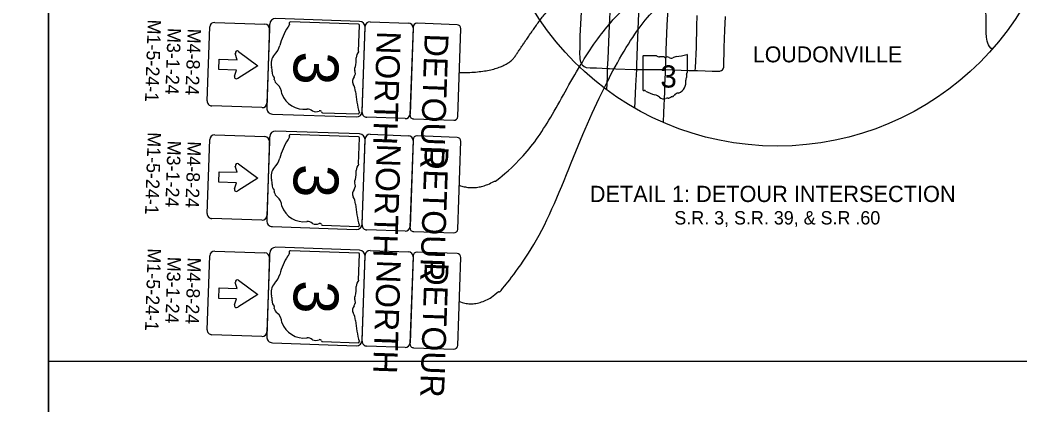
# Model space of a CAD drawing. Extents: x -15.3 to 34, y 0 to 22.
# Drawn here: x 1.2 to 11.66, y 10.54 to 14.57 of the extents above; entities that cross this region are included whole.
import ezdxf

# ---------------------------------------------------------------- set-up
doc = ezdxf.new("R2010")
doc.units = 0
for name, color, linetype in [('GM_X_City_Street', 7, 'Continuous'), ('GM_X_Corporation_Text', 7, 'Continuous'), ('GM_X_State_Route', 7, 'Continuous'), ('GM_X_State_Shield', 7, 'Continuous'), ('SC_Scratch1', 7, 'Continuous'), ('SH_Border', 7, 'Continuous'), ('SH_Text', 7, 'Continuous'), ('SN_P_Signs', 7, 'Continuous')]:
    doc.layers.add(name, color=color, linetype=linetype)

msp = doc.modelspace()

# ---------------------------------------------------------------- linework, layer by layer
at = {"layer": 'GM_X_City_Street'}
for points in [[(11.372, 14.262), (11.357, 14.274), (11.345, 14.29), (11.334, 14.308), (11.326, 14.327), (11.32, 14.348), (11.315, 14.369), (11.312, 14.39), (11.31, 14.433), (11.31, 14.543), (11.307, 14.718), (11.305, 14.784), (11.304, 14.871), (11.302, 14.981), (11.302, 15.108)], [(7.083, 14.101), (7.071, 14.127), (7.062, 14.164), (7.06, 14.233), (7.061, 14.27), (7.062, 14.341), (7.064, 14.4), (7.076, 14.655)], [(7.35, 14.062), (7.354, 14.162), (7.37, 14.512), (7.375, 14.649)], [(7.654, 14.052), (7.655, 14.102), (7.659, 14.189), (7.663, 14.297), (7.675, 14.641)], [(8.267, 14.039), (8.268, 14.068), (8.278, 14.286), (8.284, 14.505), (8.288, 14.615)], [(8.55, 14.049), (8.557, 14.058), (8.562, 14.065), (8.564, 14.075), (8.569, 14.282), (8.576, 14.462), (8.582, 14.604)], [(7.083, 14.101), (7.104, 14.082), (7.127, 14.073), (7.168, 14.069), (7.235, 14.067), (7.294, 14.065), (7.35, 14.062)], [(7.34, 13.839), (7.347, 13.97), (7.35, 14.055), (7.35, 14.062)], [(7.35, 14.062), (7.37, 14.061), (7.434, 14.058), (7.628, 14.052), (7.654, 14.052)], [(7.634, 13.647), (7.641, 13.797), (7.644, 13.884), (7.654, 14.052)], [(7.654, 14.052), (7.707, 14.05), (7.741, 14.05), (7.785, 14.05), (7.844, 14.05), (7.873, 14.05), (7.926, 14.05), (7.956, 14.05)], [(7.956, 14.05), (8.199, 14.041), (8.267, 14.039)], [(8.267, 14.039), (8.291, 14.039), (8.369, 14.037), (8.445, 14.035), (8.522, 14.035), (8.532, 14.038), (8.541, 14.042), (8.55, 14.049)]]:
    msp.add_lwpolyline(points, dxfattribs=at)
at = {"layer": 'GM_X_State_Route'}
msp.add_line((7.933, 13.497), (7.937, 13.6), dxfattribs=at)
msp.add_lwpolyline([(7.937, 13.6), (7.937, 13.601), (7.947, 13.819), (7.95, 13.885), (7.955, 14.015), (7.956, 14.05), (7.957, 14.101), (7.963, 14.254), (7.974, 14.516), (7.978, 14.629), (7.982, 14.735), (7.992, 14.973), (8.002, 15.207), (8.004, 15.235), (8.011, 15.41), (8.016, 15.515), (8.02, 15.607), (8.024, 15.694), (8.03, 15.819)], dxfattribs=at)
at = {"layer": 'GM_X_State_Shield'}
for p, q in [((7.719, 14.189), (7.719, 13.837)), ((7.86, 14.195), (7.724, 14.195)), ((8.184, 14.02), (8.184, 14.204)), ((8.184, 14.02), (8.184, 14.02))]:
    msp.add_line(p, q, dxfattribs=at)
for centre, radius, start, end in [((7.725, 14.19), 0.00538, 98.1301, 188.1301), ((7.892, 14.236), 0.0521, 231.6195, 271.1119), ((7.91, 13.998), 0.187, 80.4867, 94.9883), ((7.952, 14.192), 0.015, 219.7921, 297.1024), ((7.974, 14.151), 0.0313, 54.4667, 119.1411), ((8.015, 14.207), 0.0376, 233.8562, 294.8282), ((8.081, 14.088), 0.099, 97.3462, 120.7689), ((8.018, 14.675), 0.492, 275.8445, 288.9065), ((8.178, 14.205), 0.00517, 351.8621, 97.738), ((8.178, 14.019), 0.00553, 289.6038, 7.7341), ((8.046, 13.919), 0.123, 292.3089, 8.9858), ((8.202, 13.943), 0.0349, 136.8065, 186.9296), ((8.182, 14.006), 0.00799, 107.944, 210.337), ((8.131, 13.983), 0.048, 340.033, 23.6496), ((7.725, 13.836), 0.00542, 171.9584, 258.3066), ((7.726, 13.872), 0.0414, 267.339, 280.6039), ((7.734, 13.817), 0.0149, 29.7484, 93.2717), ((7.923, 14.133), 0.355, 240.4129, 257.1985), ((7.817, 13.679), 0.111, 47.1842, 75.836), ((7.937, 13.815), 0.0706, 230.7004, 286.2918), ((7.978, 13.693), 0.058, 85.6951, 111.2099), ((7.983, 13.789), 0.0376, 268.777, 315.5493), ((8.017, 13.754), 0.0106, 65.7517, 132.6484), ((8.012, 13.803), 0.0398, 282.8732, 323.2771), ((8.098, 13.738), 0.0674, 94.4031, 142.5768)]:
    msp.add_arc(centre, radius, start, end, dxfattribs=at)
at = {"layer": 'SH_Border'}
for points in [[(0.5, 21.5), (1.5, 21.5), (1.5, 0.5), (0.5, 0.5)], [(1.5, 21.5), (33.5, 21.5), (33.5, 0.5), (1.5, 0.5)]]:
    msp.add_lwpolyline(points, close=True, dxfattribs=at)
at = {"layer": 'SH_Text'}
msp.add_line((1.5, 11), (32, 11), dxfattribs=at)
msp.add_circle((9.125, 16.25), 3, dxfattribs=at)
for points in [[(5.798, 12.84), (6.285, 12.661), (7.504, 14.941), (8.796, 15.157), (8.904, 15.618), (9.02, 15.655)], [(5.798, 14.018), (6.273, 14.018), (6.507, 14.381), (6.828, 14.819), (8.206, 15.3), (8.557, 15.349), (8.793, 15.599), (8.86, 15.655)], [(5.798, 11.625), (6.317, 11.418), (7.553, 14.563), (8.511, 15.093), (9.076, 15.063), (9.152, 15.642), (9.308, 15.639)]]:
    msp.add_open_spline(points, degree=2, dxfattribs=at)
at = {"layer": 'SN_P_Signs'}
for p, q in [((3.24, 14.544), (3.764, 14.526)), ((4.743, 14.524), (4.032, 14.549)), ((4.866, 14.551), (5.266, 14.537)), ((3.161, 13.722), (3.188, 14.496)), ((3.813, 14.475), (3.786, 13.7)), ((4.745, 14.24), (4.755, 14.515)), ((4.783, 13.603), (4.814, 14.502)), ((5.314, 14.485), (5.283, 13.585)), ((3.488, 14.24), (3.69, 14.091)), ((3.282, 14.051), (3.286, 14.16)), ((3.286, 14.16), (3.473, 14.153)), ((3.473, 14.153), (3.455, 14.218)), ((3.469, 14.044), (3.282, 14.051)), ((3.447, 13.981), (3.469, 14.044)), ((3.69, 14.091), (3.481, 13.958)), ((3.734, 13.652), (3.209, 13.67)), ((4.368, 13.599), (4.74, 13.586)), ((4.368, 13.599), (4.368, 13.599)), ((5.231, 13.537), (4.831, 13.551)), ((3.161, 12.544), (3.188, 13.319)), ((3.24, 13.367), (3.764, 13.349)), ((3.813, 13.297), (3.786, 12.522)), ((4.743, 13.347), (4.032, 13.371)), ((4.745, 13.063), (4.755, 13.337)), ((4.783, 12.425), (4.814, 13.325)), ((4.866, 13.373), (5.266, 13.359)), ((5.314, 13.307), (5.283, 12.408)), ((3.282, 12.873), (3.286, 12.982)), ((3.286, 12.982), (3.473, 12.976)), ((3.473, 12.976), (3.455, 13.04)), ((3.488, 13.063), (3.69, 12.913)), ((3.469, 12.866), (3.282, 12.873)), ((3.69, 12.913), (3.481, 12.781)), ((3.447, 12.803), (3.469, 12.866)), ((3.734, 12.474), (3.209, 12.492)), ((4.368, 12.422), (4.74, 12.409)), ((4.368, 12.422), (4.368, 12.422)), ((5.231, 12.36), (4.831, 12.373)), ((3.24, 12.151), (3.764, 12.133)), ((4.743, 12.131), (4.032, 12.156)), ((4.866, 12.158), (5.266, 12.144)), ((3.161, 11.329), (3.188, 12.103)), ((3.813, 12.081), (3.786, 11.307)), ((4.745, 11.847), (4.755, 12.122)), ((4.783, 11.21), (4.814, 12.109)), ((5.314, 12.092), (5.283, 11.192)), ((3.473, 11.76), (3.455, 11.825)), ((3.488, 11.847), (3.69, 11.698)), ((3.282, 11.657), (3.286, 11.767)), ((3.286, 11.767), (3.473, 11.76)), ((3.469, 11.651), (3.282, 11.657)), ((3.447, 11.588), (3.469, 11.651)), ((3.69, 11.698), (3.481, 11.565)), ((3.734, 11.259), (3.209, 11.277)), ((4.368, 11.206), (4.74, 11.193)), ((4.368, 11.206), (4.368, 11.206)), ((5.231, 11.144), (4.831, 11.158))]:
    msp.add_line(p, q, dxfattribs=at)
for points in [[(4.753, 14.554), (3.879, 14.585)], [(3.814, 14.524), (3.784, 13.65)], [(4.783, 13.615), (4.814, 14.49)], [(5.314, 14.495), (5.282, 13.575)], [(5.775, 14.519), (5.356, 14.534)], [(5.782, 13.558), (5.814, 14.478)], [(3.844, 13.585), (4.719, 13.555)], [(5.321, 13.534), (5.741, 13.52)], [(4.753, 13.377), (3.879, 13.407)], [(3.814, 13.347), (3.784, 12.472)], [(4.783, 12.438), (4.814, 13.312)], [(5.314, 13.317), (5.282, 12.398)], [(5.775, 13.341), (5.356, 13.356)], [(5.782, 12.38), (5.814, 13.3)], [(3.844, 12.408), (4.719, 12.377)], [(5.321, 12.356), (5.741, 12.342)], [(4.753, 12.161), (3.879, 12.192)], [(5.775, 12.126), (5.356, 12.141)], [(3.814, 12.131), (3.784, 11.257)], [(4.783, 11.222), (4.814, 12.097)], [(5.314, 12.102), (5.282, 11.182)], [(5.782, 11.165), (5.814, 12.085)], [(3.844, 11.192), (4.719, 11.162)], [(5.321, 11.141), (5.741, 11.127)]]:
    msp.add_lwpolyline(points, dxfattribs=at)
for centre, radius, start, end in [((3.238, 14.494), 0.05, 88.0119, 178.0119), ((3.877, 14.522), 0.0625, 88.0119, 178.0119), ((4.03, 14.538), 0.011, 79.9703, 166.3185), ((4.751, 14.492), 0.0625, 358.0119, 88.0119), ((4.864, 14.501), 0.05, 88.0119, 178.0119), ((3.763, 14.476), 0.05, 358.0119, 88.0119), ((4.615, 14.118), 0.718, 148.4248, 165.2104), ((3.99, 14.521), 0.0302, 297.7603, 1.2837), ((4.103, 14.534), 0.0836, 175.3509, 188.6158), ((4.744, 14.513), 0.0109, 6.142, 96.142), ((5.264, 14.487), 0.05, 358.0119, 88.0119), ((5.354, 14.494), 0.04, 88.0119, 178.0119), ((5.774, 14.479), 0.04, 358.0119, 88.0119), ((3.476, 14.224), 0.0209, 53.4231, 195.2165), ((3.705, 14.364), 0.225, 315.1961, 343.8479), ((4.826, 14.172), 0.105, 139.6314, 179.1238), ((3.972, 14.112), 0.143, 138.7123, 194.3037), ((4.343, 14.154), 0.378, 348.4986, 3.0002), ((3.723, 14.038), 0.117, 353.707, 19.2219), ((3.915, 14.021), 0.0759, 176.7889, 223.5612), ((4.648, 14.013), 0.0632, 322.4786, 27.153), ((4.732, 14.054), 0.0304, 127.804, 205.1143), ((3.467, 13.974), 0.0209, 160.8073, 313.0215), ((3.844, 13.954), 0.0214, 333.7636, 40.6603), ((3.942, 13.96), 0.0803, 190.8851, 231.289), ((4.758, 13.927), 0.076, 141.8681, 202.8401), ((3.806, 13.792), 0.136, 2.415, 50.5887), ((4.513, 13.801), 0.2, 5.3581, 28.7808), ((5.704, 13.887), 0.994, 183.8564, 196.9184), ((3.211, 13.72), 0.05, 178.0119, 268.0119), ((4.175, 13.884), 0.249, 200.3208, 276.9977), ((3.736, 13.702), 0.05, 268.0119, 358.0119), ((3.846, 13.648), 0.0625, 178.0119, 268.0119), ((4.211, 13.567), 0.0705, 44.8184, 94.9415), ((4.298, 13.707), 0.097, 248.0449, 291.6615), ((4.341, 13.603), 0.0162, 15.9559, 118.3489), ((4.367, 13.61), 0.0112, 197.6157, 275.746), ((4.721, 13.617), 0.0625, 268.0119, 358.0119), ((4.833, 13.601), 0.05, 178.0119, 268.0119), ((4.742, 13.597), 0.0104, 259.874, 5.7499), ((5.233, 13.587), 0.05, 268.0119, 358.0119), ((5.322, 13.574), 0.04, 178.0119, 268.0119), ((5.742, 13.56), 0.04, 268.0119, 358.0119), ((3.877, 13.345), 0.0625, 88.0119, 178.0119), ((3.238, 13.317), 0.05, 88.0119, 178.0119), ((3.763, 13.299), 0.05, 358.0119, 88.0119), ((4.615, 12.94), 0.718, 148.4248, 165.2104), ((3.99, 13.343), 0.0302, 297.7603, 1.2837), ((4.03, 13.36), 0.011, 79.9703, 166.3185), ((4.103, 13.356), 0.0836, 175.3509, 188.6158), ((4.744, 13.336), 0.0109, 6.142, 96.142), ((4.751, 13.314), 0.0625, 358.0119, 88.0119), ((4.864, 13.323), 0.05, 88.0119, 178.0119), ((5.264, 13.309), 0.05, 358.0119, 88.0119), ((5.354, 13.316), 0.04, 88.0119, 178.0119), ((5.774, 13.301), 0.04, 358.0119, 88.0119), ((3.705, 13.186), 0.225, 315.1961, 343.8479), ((3.476, 13.046), 0.0209, 53.4231, 195.2165), ((3.972, 12.934), 0.143, 138.7123, 194.3037), ((4.343, 12.976), 0.378, 348.4986, 3.0002), ((4.826, 12.994), 0.105, 139.6314, 179.1238), ((3.723, 12.86), 0.117, 353.707, 19.2219), ((4.732, 12.877), 0.0304, 127.804, 205.1143), ((3.467, 12.796), 0.0209, 160.8073, 313.0215), ((3.915, 12.843), 0.0759, 176.7889, 223.5612), ((3.844, 12.777), 0.0214, 333.7636, 40.6603), ((3.942, 12.782), 0.0803, 190.8851, 231.289), ((4.758, 12.75), 0.076, 141.8681, 202.8401), ((4.648, 12.835), 0.0632, 322.4786, 27.153), ((3.806, 12.615), 0.136, 2.415, 50.5887), ((4.513, 12.624), 0.2, 5.3581, 28.7808), ((4.175, 12.707), 0.249, 200.3208, 276.9977), ((5.704, 12.709), 0.994, 183.8564, 196.9184), ((3.211, 12.542), 0.05, 178.0119, 268.0119), ((3.736, 12.524), 0.05, 268.0119, 358.0119), ((3.846, 12.47), 0.0625, 178.0119, 268.0119), ((4.211, 12.39), 0.0705, 44.8184, 94.9415), ((4.298, 12.529), 0.097, 248.0449, 291.6615), ((4.341, 12.425), 0.0162, 15.9559, 118.3489), ((4.367, 12.433), 0.0112, 197.6157, 275.746), ((4.721, 12.44), 0.0625, 268.0119, 358.0119), ((4.742, 12.419), 0.0104, 259.874, 5.7499), ((4.833, 12.423), 0.05, 178.0119, 268.0119), ((5.233, 12.41), 0.05, 268.0119, 358.0119), ((5.322, 12.396), 0.04, 178.0119, 268.0119), ((5.742, 12.382), 0.04, 268.0119, 358.0119), ((3.238, 12.101), 0.05, 88.0119, 178.0119), ((3.877, 12.129), 0.0625, 88.0119, 178.0119), ((4.03, 12.145), 0.011, 79.9703, 166.3185), ((4.103, 12.141), 0.0836, 175.3509, 188.6158), ((4.751, 12.099), 0.0625, 358.0119, 88.0119), ((4.864, 12.108), 0.05, 88.0119, 178.0119), ((5.264, 12.094), 0.05, 358.0119, 88.0119), ((5.354, 12.101), 0.04, 88.0119, 178.0119), ((3.763, 12.083), 0.05, 358.0119, 88.0119), ((4.615, 11.725), 0.718, 148.4248, 165.2104), ((3.99, 12.128), 0.0302, 297.7603, 1.2837), ((4.744, 12.12), 0.0109, 6.142, 96.142), ((5.774, 12.086), 0.04, 358.0119, 88.0119), ((3.476, 11.831), 0.0209, 53.4231, 195.2165), ((3.705, 11.971), 0.225, 315.1961, 343.8479), ((4.826, 11.779), 0.105, 139.6314, 179.1238), ((3.972, 11.719), 0.143, 138.7123, 194.3037), ((4.343, 11.761), 0.378, 348.4986, 3.0002), ((3.723, 11.645), 0.117, 353.707, 19.2219), ((3.915, 11.628), 0.0759, 176.7889, 223.5612), ((4.648, 11.62), 0.0632, 322.4786, 27.153), ((4.732, 11.661), 0.0304, 127.804, 205.1143), ((3.467, 11.581), 0.0209, 160.8073, 313.0215), ((3.844, 11.561), 0.0214, 333.7636, 40.6603), ((3.942, 11.567), 0.0803, 190.8851, 231.289), ((4.758, 11.534), 0.076, 141.8681, 202.8401), ((3.806, 11.399), 0.136, 2.415, 50.5887), ((4.175, 11.491), 0.249, 200.3208, 276.9977), ((4.513, 11.408), 0.2, 5.3581, 28.7808), ((5.704, 11.494), 0.994, 183.8564, 196.9184), ((3.211, 11.327), 0.05, 178.0119, 268.0119), ((3.736, 11.309), 0.05, 268.0119, 358.0119), ((3.846, 11.255), 0.0625, 178.0119, 268.0119), ((4.211, 11.174), 0.0705, 44.8184, 94.9415), ((4.298, 11.314), 0.097, 248.0449, 291.6615), ((4.341, 11.21), 0.0162, 15.9559, 118.3489), ((4.367, 11.217), 0.0112, 197.6157, 275.746), ((4.721, 11.224), 0.0625, 268.0119, 358.0119), ((4.742, 11.204), 0.0104, 259.874, 5.7499), ((4.833, 11.208), 0.05, 178.0119, 268.0119), ((5.233, 11.194), 0.05, 268.0119, 358.0119), ((5.322, 11.181), 0.04, 178.0119, 268.0119), ((5.742, 11.167), 0.04, 268.0119, 358.0119)]:
    msp.add_arc(centre, radius, start, end, dxfattribs=at)

# ---------------------------------------------------------------- texts
at = {"layer": 'GM_X_Corporation_Text'}
msp.add_text('LOUDONVILLE', height=0.16667, rotation=0, dxfattribs=at).set_placement((8.87, 14.126))
at = {"layer": 'GM_X_State_Shield'}
msp.add_text('3', height=0.232, dxfattribs=at).set_placement((7.901, 13.862))
at = {"layer": 'SC_Scratch1'}
for s, p in [('M1-5-24-1', (2.54, 14.575)), ('M3-1-24', (2.747, 14.487)), ('M4-8-24', (2.957, 14.48)), ('M1-5-24-1', (2.54, 13.397)), ('M3-1-24', (2.747, 13.309)), ('M4-8-24', (2.957, 13.302)), ('M1-5-24-1', (2.54, 12.182)), ('M3-1-24', (2.747, 12.094)), ('M4-8-24', (2.957, 12.087))]:
    msp.add_text(s, height=0.14, rotation=268.0119, dxfattribs=at).set_placement(p)
at = {"layer": 'SH_Text'}
for s, height, p in [('DETAIL 1: DETOUR INTERSECTION', 0.17, (7.163, 12.665)), ('S.R. 3, S.R. 39, & S.R .60', 0.14, (8.048, 12.43))]:
    msp.add_text(s, height=height, dxfattribs=at).set_placement(p)
at = {"layer": 'SN_P_Signs'}
for s, height, p in [('NORTH', 0.25, (4.938, 14.455)), ('DETOUR', 0.25, (5.437, 14.429)), ('3', 0.469, (4.071, 14.245)), ('NORTH', 0.25, (4.938, 13.277)), ('DETOUR', 0.25, (5.437, 13.251)), ('3', 0.469, (4.071, 13.067)), ('NORTH', 0.25, (4.938, 12.062)), ('DETOUR', 0.25, (5.437, 12.036)), ('3', 0.469, (4.071, 11.852))]:
    msp.add_text(s, height=height, rotation=268.0119, dxfattribs=at).set_placement(p)

doc.saveas('drawing.dxf')
